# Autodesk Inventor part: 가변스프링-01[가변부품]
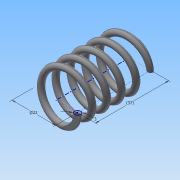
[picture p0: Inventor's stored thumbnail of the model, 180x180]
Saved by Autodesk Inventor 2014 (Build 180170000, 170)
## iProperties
Created: 2015-09
Part Number: 가변스프링-01[가변부품]
Material: 강철, 탄소
Document SubType Name: Modeling
Designer: study
Density: 7.87 g/cm^3
Appearance: 반연마
Mass: 18.6318 g
Surface Area: 32.4192 cm^2
Volume: 2.36745 cm^3
Author: study
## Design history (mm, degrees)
sketch "스케치1"
  geometry: L1 (0, 0)-(11, 0); L2 (11, 0)-(11, 25.358); L3 (11, 25.358)-(0, 25.358); L4 (0, 25.358)-(0, 0); C1 r 1.5 at (11, 0)
  constraints: 8 end point, 2 parallel, 1 centre point, 1 coincident, 1 horizontal, 1 perpendicular
  dimensions: "d0" = 22 diameter of L2 L4; "d1" = 25.35829 distance of L1.end L2.end (derived); "d2" = 3 diameter of C1
feature "코일1" sketch "스케치1" pitch "d3" = 10; turns "d5" = 5; dims "d4" = 25.35829 (= d1), "d6" = 0, angle "d7" = 90 deg, angle "d8" = 90 deg, "d9" = 0, "d10" = 0
sketch "스케치2"
  geometry: L1 (-12.5, 0)-(-9.5, 0) reference; L2 (-12.5, 0)-(-9.5, 0) reference; 1 further point
  constraints: 2 horizontal alignment
extrude "돌출1" cut sketch "스케치2" stored distance "d11" = 10; taper "d12" = 0 deg
node "작업 평면1"
sketch "스케치3"
  geometry: L1 (-9.5, 0)-(-12.5, 0) reference; 1 further point
  constraints: 1 horizontal alignment
extrude "돌출2" cut sketch "스케치3" stored distance "d14" = 10; taper "d15" = 0 deg
node "솔리드1"
node "절단 모서리 투영1"
node "절단 모서리 투영2"
node "절단 모서리 투영3"
other parameters: "d13" = 25.35829 (= d1)
